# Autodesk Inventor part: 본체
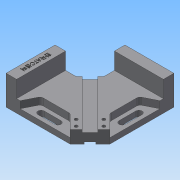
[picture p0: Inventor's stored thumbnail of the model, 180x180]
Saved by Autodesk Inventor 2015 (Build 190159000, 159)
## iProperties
Created: 2019-04
Part Number: 본체
Material: 알루미늄 6061
Document SubType Name: Modeling
Designer: user
Density: 2.7 g/cm^3
Appearance: 기본값
Mass: 601.509 g
Surface Area: 426.536 cm^2
Volume: 222.781 cm^3
Author: user
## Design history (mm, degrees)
sketch "스케치1"
  geometry: L1 (60, 60)-(-60, 60); L2 (-60, 60)-(-60, -60); L3 (-60, -60)-(60, -60); L4 (60, -60)-(60, 60); L5 (60, 60)-(-60, -60); L6 (-60, 60)-(60, -60); 1 further point
  constraints: 12 end point, 2 midpoint, 2 parallel, 1 horizontal, 1 perpendicular
  dimensions: "d0" = 120 distance of L2.end L3.end; "d1" = 120 distance of L1.end L2.end
extrude "돌출1" new body sketch "스케치1" distance "d2" = 42; taper "d3" = 0 deg
sketch "스케치2"
  geometry: L1 (60, 60)-(-60, 60) reference; L2 (-60, 60)-(-60, -60) reference; L3 (60, -60)-(-45, -60); L4 (-45, -60)-(-45, 45); L5 (-45, 45)-(60, 45); L6 (60, 45)-(60, -60); 1 further point
  constraints: 8 end point, 2 parallel, 1 horizontal, 1 perpendicular
  dimensions: "d4" = 15 distance between parallel lines of L2 L4; "d5" = 15 distance between parallel lines of L1 L5
extrude "돌출2" cut sketch "스케치2" distance "d6" = 24; taper "d7" = 0 deg
sketch "스케치4"
  geometry: L1 (60, 45)-(60, -60) reference; L2 (60, -60)-(-45, -60) reference; L3 (60, -60)-(31.716, -60); L4 (60, -31.716)-(60, -60); L5 (31.716, -60)-(60, -31.716); 1 further point
  constraints: 6 end point, 2 point on line, 1 collinear
  dimensions: "d13" = 20 distance from line of L5 L1.end; "d14" = 45 deg angle of L1 L5
extrude "돌출3" cut sketch "스케치4" stored distance "d15" = 24; taper "d16" = 0 deg
sketch "스케치5"
  geometry: L1 (-60, 60)-(-10, 60); L2 (-10, 60)-(-10, 29.806); L3 (-29.806, 10)-(-60, 10); L4 (-60, 10)-(-60, 60); L5 (-29.806, 10)-(-10, 29.806); L6 (31.716, -60)-(60, -31.716) reference; 1 further point
  constraints: 10 end point, 3 parallel, 1 horizontal, 1 perpendicular
  dimensions: "d17" = 50 distance of L1.start L3.end; "d18" = 50 distance of L1.end L1.start; "d40" = 93 distance between parallel lines of L6 L5
extrude "돌출4" cut sketch "스케치5" stored distance "d21" = 24; taper "d22" = 0 deg
sketch "스케치6"
  geometry: L1 (31.716, -60)-(-45, -60) reference; L2 (31.716, -60)-(60, -31.716) reference; L3 (-40, -60)-(-30, -40); L4 (-30, -40)-(11.716, -40); L5 (11.716, -40)-(31.716, -60); L6 (-40, -60)-(31.716, -60); L7 (-60, 10)-(-60, -60) reference; L8 (60, 60)-(-10, 60) reference; 1 further point
  constraints: 8 end point, 1 collinear, 1 horizontal, 1 point on line
  dimensions: "d23" = 90 deg angle of L2 L5; "d24" = 20 distance between parallel lines of L1 L4; "d25" = 30 distance from line of L7 L3.end; "d26" = 20 distance from line of L7 L3.start
extrude "돌출5" cut sketch "스케치6" distance "d31" = 10; taper "d32" = 0 deg
sketch "스케치7"
  geometry: L1 (-30, -40)-(11.716, -40) reference; L2 (-20, -50)-(4, -50); L3 (-20, -54.5)-(4, -54.5); L4 (4, -45.5)-(-20, -45.5); L5 (-60, -60)-(-45, -60) reference; L6 (-60, 10)-(-60, -60) reference; A1 r 4.5 centre (-20, -50) between (-20, -45.5) and (-20, -54.5); A2 r 4.5 centre (4, -50) between (4, -54.5) and (4, -45.5); 2 further points
  constraints: 8 end point, 4 point on circle, 4 tangent, 2 centre point, 2 parallel, 1 midpoint
  dimensions: "d33" = 4.5 radius of A1; "d34" = 24 distance of L2.end L2.start; "d35" = 10 distance from line of L5 L2.start; "d36" = 40 distance from line of L6 L2.start
extrude "돌출6" cut sketch "스케치7" stored distance "d37" = 10; taper "d38" = 0 deg
node "작업 평면1"
sketch "스케치9"
  geometry: L1 (-10, 29.806)-(-29.806, 10) reference; L2 (31.716, -60)-(60, -31.716) reference; L3 (40.201, -51.515)-(-25.56, 14.246); L4 (-14.246, 25.56)-(51.515, -40.201); L5 (40.201, -51.515)-(51.515, -40.201); L6 (-25.56, 14.246)-(-14.246, 25.56); L7 (-19.903, 19.903)-(45.858, -45.858); 1 further point
  constraints: 10 end point, 4 point on line, 3 perpendicular, 2 collinear, 2 midpoint, 1 other
  dimensions: "d41" = 16 distance between parallel lines of L4 L3
extrude "돌출7" cut sketch "스케치9" distance "d42" = 3.5; taper "d43" = 0 deg
sketch "스케치10"
  geometry: L1 (-29.806, -10)-(-10, -29.806) reference; L2 (60, 31.716)-(31.716, 60) reference; L3 (50.101, 41.615)-(-15.66, -24.146); L4 (-24.146, -15.66)-(41.615, 50.101); L5 (50.101, 41.615)-(41.615, 50.101); L6 (-15.66, -24.146)-(-24.146, -15.66); L7 (-19.903, -19.903)-(45.858, 45.858); 1 further point
  constraints: 10 end point, 4 point on line, 3 perpendicular, 2 collinear, 2 midpoint, 1 other
  dimensions: "d45" = 12 distance of L3.start L4.end
extrude "돌출8" cut sketch "스케치10" distance "d46" = 3; taper "d47" = 0 deg
hole "구멍1" diameter "d50" = 4.5; stored, may be unused: countersink angle "d54" = 90 deg, drill point angle "d56" = 118 deg; dims "d48" = 6, "d51" = 6, "d52" = 8, "d53" = 10, "d55" = 8, "d58" = 6
sketch "스케치12"
  geometry: L1 (-45, 10)-(-60, 10) reference; L2 (-45, -60)-(-45, 10) reference; 2 further points
  constraints: 1 other
  dimensions: "d61" = 35 distance from line of L1 point (-52.5, -25); "d62" = 7.5 distance from line of L2 point (-52.5, -25)
feature "엠보싱1" sketch "스케치12" dims "d0" = 120, "d1" = 120, "d63" = 0.5, "d64" = 0
fillet "모깎기1" dims "d65" = 5
node "솔리드1"
mirror "대칭1"
pattern_linear "직사각형 패턴1" dims "d60" = 12
mirror "대칭2"
